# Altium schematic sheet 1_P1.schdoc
size 309 x 223 mm; Symbol: Sheet-Symbol_A4; Device: Sheet-Symbol_A4; @Page Name: P1; @Create Date: 2023-04-30; @Page Count: 2; @Page No: 1; @Project Name: ESP32 Board V4.0; @Schematic Name: Schematic2_1; @Update Date: 2023-05-01; Company: 嘉立创EDA; Page Size: A4; Version: V1.0; attr-name: 77777777777777
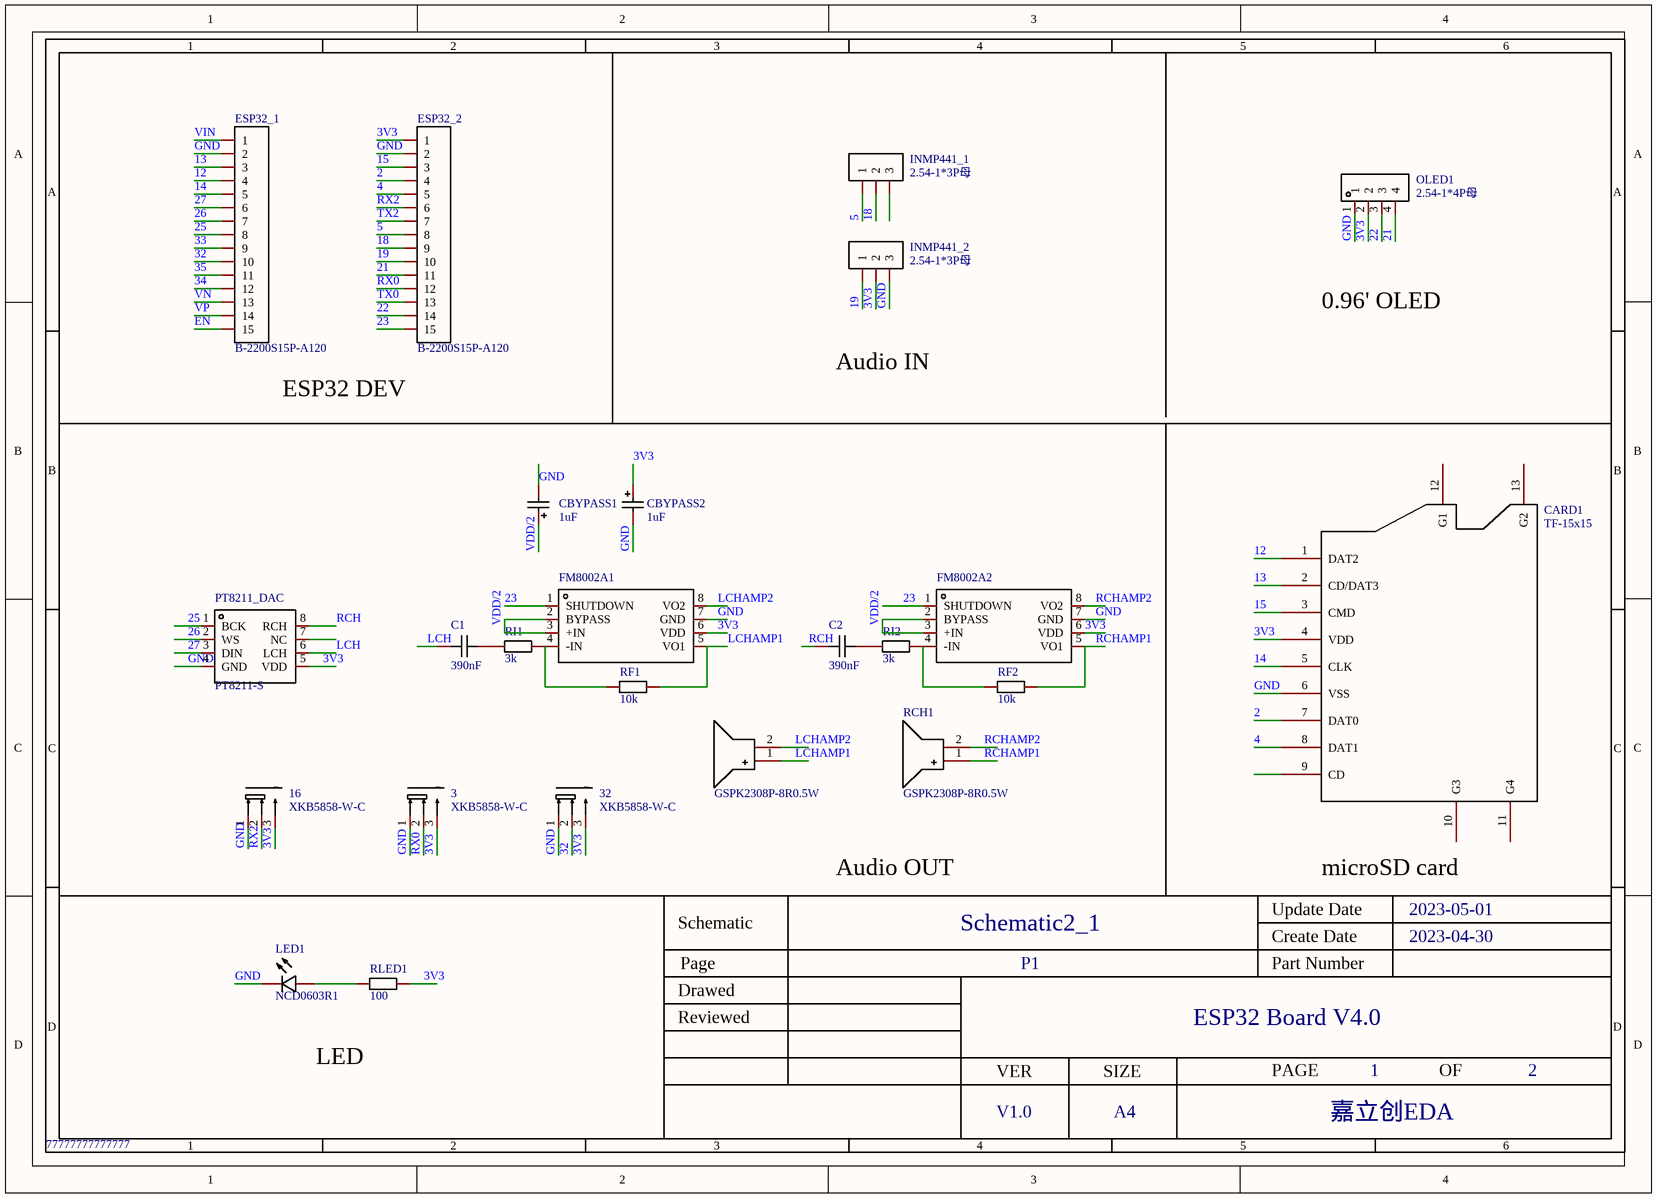
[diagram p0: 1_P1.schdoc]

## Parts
3  XKB5858-W-C  [SW-TH_XKB5858-Z-C]
16  XKB5858-W-C  [SW-TH_XKB5858-Z-C]
32  XKB5858-W-C  [SW-TH_XKB5858-Z-C]
C1  390nF  [C0603]
C2  390nF  [C0603]
CARD1  TF-15x15  [TF-SMD_TF-15-15]
CBYPASS1  1uF  [CASE-A_3216]
CBYPASS2  1uF  [CASE-A_3216]
ESP32_1  B-2200S15P-A120  [HDR-TH_15P-P2.54-V-F-1]
ESP32_2  B-2200S15P-A120  [HDR-TH_15P-P2.54-V-F-1]
FM8002A1  FM8002A  [SOP-8_L4.9-W3.9-P1.27-LS6.0-BL]  (value not drawn)
FM8002A2  FM8002A  [SOP-8_L4.9-W3.9-P1.27-LS6.0-BL]  (value not drawn)
INMP441_1  2.54-1*3P母  [HDR-TH_3P-P2.54-V-F]
INMP441_2  2.54-1*3P母  [HDR-TH_3P-P2.54-V-F]
LCH1  GSPK2308P-8R0.5W  [SPK-TH_BD23.0-P10.00-D0.8-L-RD]
LED1  NCD0603R1  [LED0603-RD_RED]
OLED1  2.54-1*4P母  [HDR-TH_4P-P2.54-V-F]
PT8211_DAC  PT8211-S  [SOP-8_L4.9-W3.9-P1.27-LS6.0-BL]
RCH1  GSPK2308P-8R0.5W  [SPK-TH_BD23.0-P10.00-D0.8-L-RD]
RF1  10k  [R0603]
RF2  10k  [R0603]
RI1  3k  [R0603]
RI2  3k  [R0603]
RLED1  100  [R0603]

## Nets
2: CARD1.7(DAT0) ESP32_2.4
3V3: 3.3 16.3 32.3 CARD1.4(VDD) CBYPASS2.1 ESP32_2.1 FM8002A1.6(VDD) FM8002A2.6(VDD) INMP441_2.2 OLED1.2 PT8211_DAC.5(VDD) RLED1.2
4: CARD1.8(DAT1) ESP32_2.5
5: ESP32_2.8 INMP441_1.1
12: CARD1.1(DAT2) ESP32_1.4
13: CARD1.2(CD/DAT3) ESP32_1.3
14: CARD1.5(CLK) ESP32_1.5
15: CARD1.3(CMD) ESP32_2.3
18: ESP32_2.9 INMP441_1.2
19: ESP32_2.10 INMP441_2.1
21: ESP32_2.11 OLED1.4
22: ESP32_2.14 OLED1.3
23: ESP32_2.15 FM8002A1.1(SHUTDOWN) FM8002A2.1(SHUTDOWN)
25: ESP32_1.8 PT8211_DAC.1(BCK)
26: ESP32_1.7 PT8211_DAC.2(WS)
27: ESP32_1.6 PT8211_DAC.3(DIN)
32: 32.2 ESP32_1.10
33: ESP32_1.9
34: ESP32_1.12
35: ESP32_1.11
EN: ESP32_1.15
GND: 3.1 16.1 32.1 CARD1.6(VSS) CBYPASS1.2 CBYPASS2.2 ESP32_1.2 ESP32_2.2 FM8002A1.7(GND) FM8002A2.7(GND) INMP441_2.3 LED1.1(K) OLED1.1 PT8211_DAC.4(GND)
LCH: C1.1 PT8211_DAC.6(LCH)
LCHAMP1: FM8002A1.5(VO1) LCH1.1(+) RF1.2
LCHAMP2: FM8002A1.8(VO2) LCH1.2(-)
RCH: C2.1 PT8211_DAC.8(RCH)
RCHAMP1: FM8002A2.5(VO1) RCH1.1(+) RF2.2
RCHAMP2: FM8002A2.8(VO2) RCH1.2(-)
RX0: 3.2 ESP32_2.12
RX2: 16.2 ESP32_2.6
TX0: ESP32_2.13
TX2: ESP32_2.7
VDD/2: CBYPASS1.1 FM8002A1.2(BYPASS) FM8002A1.3(+IN) FM8002A2.2(BYPASS) FM8002A2.3(+IN)
VIN: ESP32_1.1
VN: ESP32_1.13
VP: ESP32_1.14
NetC1_2: C1.2 RI1.1
NetC2_2: C2.2 RI2.1
NetFM8002A1_4: FM8002A1.4(-IN) RF1.1 RI1.2
NetFM8002A2_4: FM8002A2.4(-IN) RF2.1 RI2.2
NetLED1_2: LED1.2(A) RLED1.1

Not connected (* = marked no-connect by the designer): CARD1 9(CD) 10(G3) 11(G4) 12(G1) 13(G2); INMP441_1 3; PT8211_DAC 7(NC)

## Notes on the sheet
- 0.96' OLED
- ESP32 DEV
- Audio IN
- Audio OUT
- microSD card
- LED

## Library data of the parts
3 16 32 = XKB5858-W-C: 触点电流:100mA;额定电压(AC):250V;额定电压(DC):30V;绝缘电阻:100MΩ;电路结构:-;安装方式:卧插;自锁/无锁:无锁;按键形状:矩形按钮;按键/盖帽颜色:白色;带灯:无;引脚样式:PC引脚;作用力:160gf@±80gf;防护等级:-;工作温度:-15℃~+55℃;机械寿命:10000;; Manufacturer: XKBConnectivity(中国星坤); Add into BOM: yes; Contact Current: 100mA; Voltage Rating (AC): 250V; Voltage Rating (DC): 30V; Insulation Resistance: 100MΩ; Self Lock / No Lock: 无锁; Actuator Style: 矩形按钮; Actuator/Cap Color: 白色; With Lamp: 无; Pin Style: PC引脚; Mechanical Life: 10000
C1 C2 = GCM188R71C394KA55D: 容值:390nF;精度:±10%;额定电压:16V;材质(温度系数):X7R;; Manufacturer: muRata(村田); Add into BOM: yes; Tolerance: ±10%; Voltage Rated: 16V; Temperature Coefficient: X7R
CARD1 = TF-15x15: 卡连接方式:自弹式;卡类型:MicroSD卡(TF卡);连接器类型:卡座;本体最大高度:-;触头材质:-;触头镀层:-;工作温度范围:-;焊接温度(最大值):-;; Manufacturer: SOFNG(硕方); Symbol: TF-15×15; Add into BOM: yes; Card Connection Mode: 自弹式; Connector Type: 卡座
CBYPASS1 CBYPASS2 = TAJA105K016RNJ: 容值:1uF;精度:±10%;额定电压:16V;等效串联电阻:11Ω;工作温度:-55℃~+125℃;; Manufacturer: KyoceraAVX; Add into BOM: yes; Tolerance: ±10%; Rated Voltage: 16V; Equivalent Series Resistance(ESR): 11Ω
ESP32_1 ESP32_2 = B-2200S15P-A120: 排数:单排;总孔位数:15;间距:2.54mm;插孔结构:1x15P;行距:-;安装类型:直插;塑高:-;触头材质:黄铜;触头镀层:-;; Manufacturer: Ckmtw(灿科盟); Symbol: Header-Female-2.54_1x15; Add into BOM: yes; Number of Holes: 15; Pitch: 2.54mm; Holes Structure: 1x15P
FM8002A1 FM8002A2 = FM8002A: 功放类型:-;扬声器通道数:1通道(单声道);输出功率:2Wx1@4Ω;; Manufacturer: FM(富满); Add into BOM: yes; Supply Voltage: 2.5V~5.5V
INMP441_1 INMP441_2 = 2.54-1*3P母: 排数:单排;总孔位数:3;间距:2.54mm;行距:-;安装类型:直插;塑高:-;触头材质:-;触头镀层:金;; Manufacturer: BOOMELE(博穆精密); Symbol: Header-Female-2.54_1x3; Add into BOM: yes; Number of Holes: 3; Pitch: 2.54mm
LCH1 RCH1 = GSPK2308P-8R0.5W: Manufacturer: INGHAi(赢海); Add into BOM: yes
LED1 = NCD0603R1_C84263: 发光颜色:红灯;; Manufacturer: 国星光电; Symbol: FC-DA1608HRK-620D; Add into BOM: yes; Emitted Color: 红灯
OLED1 = 2.54-1*4P母: 排数:单排;总孔位数:4;间距:2.54mm;插孔结构:1x4P;行距:-;安装类型:直插;圆孔/方孔:方孔;额定电流:3A;额定电压:-;插孔方向:顶部;塑高:-;触头材质:青铜;触头镀层:-;工作温度范围:-40℃~+105℃;焊接温度(最大值):-;; Manufacturer: BOOMELE(博穆精密); Add into BOM: yes; Number of Holes: 4; Pitch: 2.54mm; Holes Structure: 1x4P; Circular Hole / Square Hole: 方孔; Current Rating (Max): 3A; Holes Direction: 顶部
PT8211_DAC = PT8211-S: Manufacturer: PTC(普诚); Add into BOM: yes
RF1 RF2 RI1 RI2 RLED1 = Res_0603: Symbol: 电阻; Convert to PCB: yes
